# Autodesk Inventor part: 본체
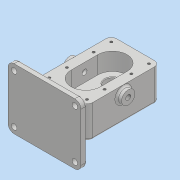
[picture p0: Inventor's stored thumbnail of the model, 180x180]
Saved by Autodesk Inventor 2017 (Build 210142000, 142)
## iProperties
Part Number: 본체
Material: 일반
Document SubType Name: Modeling
Designer: MRC
Density: 1 g/cm^3
Appearance: 기본값
Author: MRC
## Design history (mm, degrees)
sketch "스케치1"
  geometry: L1 (-40, 38)-(40, 38); L2 (40, 38)-(40, -82); L3 (40, -82)-(-40, -82); L4 (-40, -82)-(-40, 38); C1 r 19 at (0, 0); 2 further points
  constraints: 8 end point, 2 parallel, 1 centre point, 1 coincident, 1 horizontal, 1 midpoint, 1 perpendicular, 1 vertical alignment
  dimensions: "d0" = 38 diameter of C1; "d1" = 80 distance of L1.start L1.end; "d2" = 120 distance of L1.end L2.end; "d3" = 38 distance of point (0, 0) point (0, 38)
extrude "돌출1" new body sketch "스케치1" distance "d4" = 14; taper "d5" = 0 deg
extrude "돌출2" join sketch "스케치1" distance "d6" = 39; taper "d7" = 0 deg
fillet "모깎기1" dims "d8" = 9
sketch "스케치2"
  geometry: L1 (-31, -82)-(31, -82) reference; L2 (31, 38)-(-31, 38) reference; L3 (-24, 0)-(-24, -44); L4 (24, 0)-(24, -44); A1 r 24 centre (0, 0) between (24, 0) and (-24, 0); A2 r 24 centre (0, -44) between (-24, -44) and (24, -44); 1 further point
  constraints: 4 end point, 4 point on circle, 2 centre point, 2 tangent, 1 coincident, 1 parallel
  dimensions: "d9" = 48 diameter of A1; "d10" = 48 diameter of A2; "d12" = 38 distance from line of A1.centre L2; "d13" = 38 distance from line of L1 A2.centre; "d14" = 92 dimension on A2 A1; "d15" = 48 distance between parallel lines of L4 L3
extrude "돌출3" cut sketch "스케치2" distance "d16" = 29; taper "d17" = 0 deg
sketch "스케치4"
  geometry: C1 r 19 at (0, 0); 1 further point
  constraints: 1 centre point, 1 coincident
  dimensions: "d18" = 38 diameter of C1
extrude "돌출4" join sketch "스케치4" distance "d19" = 17; taper "d20" = 0 deg
sketch "스케치6"
  geometry: C1 r 12.5 at (0, 0); C2 r 12.5 at (0, -44); A1 r 24 centre (0, 0) between (24, 0) and (-24, 0) reference; A2 r 24 centre (0, -44) between (-24, -44) and (24, -44) reference
  constraints: 2 centre point, 2 coincident
  dimensions: "d21" = 25 diameter of C1; "d22" = 25 diameter of C2
extrude "돌출5" cut sketch "스케치6" distance "d23" = 15; taper "d24" = 0 deg
hole "구멍1" diameter "d27" = 17; stored, may be unused: countersink angle "d31" = 90 deg, drill point angle "d33" = 0 deg; dims "d25" = 10, "d26" = 10, "d28" = 6, "d29" = 28, "d30" = 7.3, "d32" = 26
fillet "모깎기2" dims "d34" = 0.5
sketch "스케치8"
  geometry: L1 (0, -56)-(0, -55.3); L2 (14, -56)-(-14, -56) reference; L3 (0, -55.3)-(14, -55.3); L4 (14, -55.3)-(14.404, -56); L5 (-19, -56)-(19, -56) reference; L6 (0, -56)-(14.404, -56); L7 (-19, -56)-(19, -56) reference; L8 (19, -39)-(-19, -39) reference; L9 (14, -56)-(-14, -56) reference; L10 (-14, -49.2)-(14, -49.2) reference; L11 (14, -55.3)-(14, -56); L12 (14.404, -56)-(14, -56); 1 further point
  constraints: 12 end point, 1 collinear, 1 horizontal, 1 midpoint, 1 parallel, 1 perpendicular, 1 point on line
  dimensions: "d35" = 0.7 distance of L1.start L1.end; "d36" = 0.7 distance between parallel lines of L2 L3; "d40" = 60 deg angle of L5 L4
revolve "회전1" sketch "스케치8" stored, may be unused: angle "d41" = 90 deg
sketch "스케치9"
  geometry: A1 r 9 centre (-31, -73) between (-40, -73) and (-31, -82) reference; A2 r 9 centre (31, -73) between (31, -82) and (40, -73) reference; A3 r 9 centre (31, 29) between (40, 29) and (31, 38) reference; A4 r 9 centre (-31, 29) between (-31, 38) and (-40, 29) reference; 8 further points
  constraints: 4 coincident, 4 vertical alignment
  dimensions: "d42" = 29 distance of point (31, 0) point (31, 29); "d43" = 44 distance of point (31, -44) point (31, 0); "d44" = 29 distance of point (-31, 0) point (-31, 29); "d45" = 44 distance of point (-31, -44) point (-31, 0)
hole "구멍2" sketch "스케치9" at (-31, 29), (31, 29), (-31, 0), (-31, -44), (-31, -73), (31, -73), (31, -44), (31, 0) diameter "d46" = 4.134; stored, may be unused: countersink angle "d50" = 90 deg, drill point angle "d52" = 118 deg; dims "d47" = 10, "d48" = 28, "d49" = 7.3, "d51" = 12
sketch "스케치10"
  geometry: C1 r 11 at (-39, 51); 1 further point
  constraints: 1 centre point, 1 vertical alignment
  dimensions: "d53" = 22 diameter of C1; "d54" = 22 distance of C1.centre point (-39, 73)
extrude "돌출6" join sketch "스케치10" distance "d55" = 8; taper "d56" = 0 deg
hole "구멍3" diameter "d59" = 8.376; stored, may be unused: countersink angle "d63" = 90 deg, drill point angle "d65" = 118 deg; dims "d57" = 10, "d58" = 10, "d60" = 20, "d61" = 28, "d62" = 7.3, "d64" = 27.3
sketch "스케치12"
  geometry: L1 (-102, 44)-(-112, 44); L2 (-112, 44)-(-112, -56); L3 (-112, -56)-(-102, -56); L4 (-102, -56)-(-102, 44); L5 (-102, 14)-(-82, 2.453); L6 (-82, -27.453)-(-102, -39); L7 (38, 14)-(38, -39) reference; L8 (-19, -56)-(19, -56) reference; L9 (-82, -39)-(-82, 14) reference; 1 further point
  constraints: 12 end point, 5 point on line, 2 parallel, 1 horizontal, 1 perpendicular
  dimensions: "d69" = 150 distance between parallel lines of L7 L2; "d70" = 10 distance of L2.end L3.end; "d71" = 100 distance of L1.end L2.end; "d72" = 17 distance from line of L3 L6.end; "d73" = 53 distance of L5.start L6.end; "d74" = 60 deg angle of L6 L4; "d76" = 60 deg angle of L4 L5
extrude "돌출7" join sketch "스케치12" stored distance "d77" = 120; taper "d78" = 0 deg
extrude "돌출8" join sketch "스케치12" stored distance "d79" = 48; taper "d80" = 0 deg
fillet "모깎기3" dims "d81" = 10
fillet "모깎기4" dims "d82" = 3
fillet "모깎기5" dims "d83" = 3
sketch "스케치13"
  geometry: A1 r 7 centre (100, -7) between (107, -7) and (100, 0) reference; A2 r 7 centre (0, -7) between (0, 0) and (-7, -7) reference; A3 r 7 centre (0, -87) between (-7, -87) and (0, -94) reference; A4 r 7 centre (100, -87) between (100, -94) and (107, -87) reference; 5 further points
  constraints: 4 coincident
hole "구멍4" sketch "스케치13" at (0, -87), (0, -7), (100, -7), (100, -87) diameter "d84" = 9; stored, may be unused: countersink angle "d88" = 90 deg, drill point angle "d90" = 118 deg; dims "d85" = 20, "d86" = 28, "d87" = 7.3, "d89" = 27.3
fillet "모깎기6" dims "d91" = 3
sketch "스케치14"
  geometry: L1 (0, -97)-(100, -97) reference; L2 (-10, -7)-(-10, -87) reference; 2 further points
  constraints: 1 other
  dimensions: "d92" = 10 distance from line of point (50, -87) L1; "d93" = 60 distance from line of point (50, -87) L2
feature "엠보싱1" sketch "스케치14" dims "d9" = 48, "d10" = 48, "d12" = 38, "d13" = 38, "d14" = 92, "d15" = 48, "d94" = 0.5, "d95" = 0
chamfer "모따기1" distance "d96" = 1; stored, may be unused: second distance "d97" = 2, angle "d98" = 45 deg
node "솔리드1"
mirror "미러1"
node "투영된 루프1"
node "투영된 루프2"
